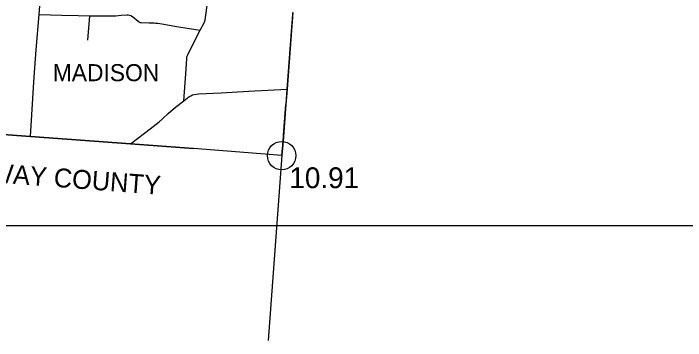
# Model space of a CAD drawing. Extents: x 1729596 to 1934326, y 644115 to 911751.
# Drawn here: x 1863218 to 1898662, y 644115 to 661397 of the extents above; entities that cross this region are included whole.
import ezdxf

# ---------------------------------------------------------------- set-up
doc = ezdxf.new("R2010")
doc.units = 0
for name, color, linetype in [('Default', 7, 'Continuous'), ('GM_X_Adjacent_County', 7, 'Continuous'), ('GM_X_Adjacent_County_Text', 7, 'Continuous'), ('GM_X_County', 7, 'Continuous'), ('GM_X_County_Road', 7, 'Continuous'), ('GM_X_State_Route', 7, 'Continuous'), ('GM_X_Township_Road', 7, 'Continuous'), ('GM_X_Township_Text', 7, 'Continuous'), ('SC_Scratch1', 7, 'Continuous')]:
    doc.layers.add(name, color=color, linetype=linetype)

msp = doc.modelspace()

# ---------------------------------------------------------------- linework, layer by layer
at = {"layer": 'Default'}
msp.add_circle((1877360, 653884), 750, dxfattribs=at)
msp.add_circle((1877360, 653884), 750, dxfattribs=at)
at = {"layer": 'GM_X_Adjacent_County'}
msp.add_line((1877380, 653885), (1876647, 644115), dxfattribs=at)
at = {"layer": 'GM_X_County'}
msp.add_lwpolyline([(1877958, 661450), (1877649, 657393), (1877591, 656580), (1877433, 654641), (1877380, 653888), (1872712, 654264), (1869398, 654514), (1864124, 654894), (1861474, 655088)], dxfattribs=at)
at = {"layer": 'GM_X_County_Road'}
for points in [[(1864569, 661334), (1864755, 663649), (1864875, 665092), (1864872, 665174), (1864827, 665345), (1864754, 665527), (1864756, 665581)], [(1872662, 659716), (1873068, 660509), (1873300, 660936), (1873325, 661064), (1873471, 662054), (1873523, 662158), (1873562, 662223)], [(1864124, 654894), (1864310, 658049), (1864422, 659478), (1864569, 661334)], [(1872302, 658199), (1872358, 659001), (1872365, 659097), (1872407, 659218), (1872662, 659716)], [(1869398, 654514), (1870125, 655063), (1870427, 655297), (1870901, 655676), (1871071, 655826), (1871383, 656105), (1871761, 656444), (1872202, 656780), (1872302, 658199)], [(1872202, 656780), (1872465, 656982), (1872570, 657045), (1872667, 657091), (1872757, 657116), (1872975, 657143), (1874171, 657208), (1875618, 657288), (1877649, 657393)], [(1857372, 655380), (1858836, 655268), (1861474, 655088), (1864124, 654894), (1869398, 654514)]]:
    msp.add_lwpolyline(points, dxfattribs=at)
at = {"layer": 'GM_X_State_Route'}
for points in [[(1877949, 661344), (1877958, 661450)], [(1877880, 660436), (1877949, 661344)], [(1877593, 656608), (1877649, 657393), (1877880, 660436)], [(1877478, 655196), (1877591, 656580), (1877593, 656608)], [(1877380, 653888), (1877433, 654641), (1877478, 655196)]]:
    msp.add_lwpolyline(points, dxfattribs=at)
at = {"layer": 'GM_X_Township_Road'}
for points in [[(1864569, 661334), (1865771, 661306), (1866628, 661287), (1867244, 661275), (1867254, 661275), (1867914, 661265), (1868625, 661276), (1868895, 661302), (1869189, 661319), (1869267, 661318), (1869343, 661305), (1869405, 661280), (1869496, 661226), (1869796, 660991), (1869852, 660945), (1869893, 660924), (1869961, 660915), (1870383, 660898), (1870647, 660894), (1870717, 660887), (1870831, 660879), (1871146, 660826), (1871808, 660712), (1872499, 660597), (1873068, 660509)], [(1867144, 659985), (1867244, 661275)], [(1869398, 654514), (1872712, 654264)]]:
    msp.add_lwpolyline(points, dxfattribs=at)
at = {"layer": 'SC_Scratch1'}
msp.add_lwpolyline([(1730291, 784675), (1926541, 784675), (1926541, 650175), (1730291, 650175)], close=True, dxfattribs=at)

# ---------------------------------------------------------------- texts
at = {"layer": 'Default'}
msp.add_text('10.91', height=1100, dxfattribs=at).set_placement((1877768, 652166))
at = {"layer": 'GM_X_Adjacent_County_Text'}
msp.add_text('PICKAWAY COUNTY', height=1000, rotation=355.6868, dxfattribs=at).set_placement((1857908, 652798))
at = {"layer": 'GM_X_Township_Text'}
msp.add_text('MADISON', height=900, rotation=0, dxfattribs=at).set_placement((1865291, 657817))

doc.saveas('drawing.dxf')
